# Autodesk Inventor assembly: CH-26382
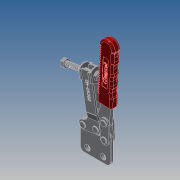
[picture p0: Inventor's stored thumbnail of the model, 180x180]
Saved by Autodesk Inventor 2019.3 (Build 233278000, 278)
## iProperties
Company: Î¢ÈíÖÐ¹ú
Created: 2012-09
Part Number: CH-26382
Material: Ogólny
Description: STEP AP203
Document SubType Name: Assembly
Designer: CADENGINEERING4
Stock Number: DOCISKI POZIOME
Sending System: SolidWorks 2010
Preprocessor: SwSTEP 2.0
Title: CH-26382.STEP
Author: Î¢ÈíÓÃ»§
Revision Number: ÈÎºÎ
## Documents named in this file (10)
- E:\STRONA\Horizontal toggle clamp\CH-26382\CH-26382_OTWARTY.iam
- E:\STRONA\Horizontal toggle clamp\CH-26382\M8.ipt
- E:\STRONA\Horizontal toggle clamp\CH-26382\01.ipt
- E:\STRONA\Horizontal toggle clamp\CH-26382\25382-04.ipt
- E:\STRONA\Horizontal toggle clamp\CH-26382\25382-05.ipt
- E:\STRONA\Horizontal toggle clamp\CH-26382\26382-02.ipt
- E:\STRONA\Horizontal toggle clamp\CH-26382\26382-01.ipt
- E:\STRONA\Horizontal toggle clamp\CH-26382\086512.ipt
- E:\STRONA\Horizontal toggle clamp\CH-26382\FW380.ipt
- E:\STRONA\Horizontal toggle clamp\CH-26382\25382-03.ipt
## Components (15 placed, 15 different names)
1. M8_1 — Równoległe:3, Zestawiające:6, Zestawiające:9
2. 01_2 — Zestawiające:1, Zestawiające:2, Zestawiające:8
3. M8_3 — Zestawiające:12, Zestawiające:13
4. 25382-04_4 — Zestawiające:15, Zestawiające:18, Zestawiające:19, Zestawiające:20, Zestawiające:21, Zestawiające:22, Zestawiające:25, Kątowe:1
5. 25382-05_5 — Zestawiające:31, Zestawiające:32
6. 25382-05_6 — Zestawiające:25, Zestawiające:33, Zestawiające:34
7. 26382-02_7 — Równoległe:1, Zestawiające:7, Zestawiające:11, Zestawiające:14, Zestawiające:26, Zestawiające:27, Zestawiające:28, Zestawiające:29, Zestawiające:30, Zestawiające:31, Zestawiające:32
8. 25382-05_8 — Zestawiające:20, Zestawiające:21
9. 26382-01_9 — Zestawiające:15, Zestawiające:16, Zestawiające:17, Zestawiające:18, Zestawiające:26, Zestawiające:27, Kątowe:1
10. 25382-04_10 — Zestawiające:16, Zestawiające:17, Zestawiające:19, Zestawiające:33
11. 086512_11 — Równoległe:3, Zestawiające:5, Zestawiające:9, Zestawiające:10, Zestawiające:12, Zestawiające:14
12. FW380_12 — Równoległe:1, Równoległe:2, Zestawiające:5, Zestawiające:6, Zestawiające:7
13. FW380_13 — Równoległe:2, Zestawiające:10, Zestawiające:11, Zestawiające:13
14. 25382-03_14 — Zestawiające:1, Zestawiające:2, Zestawiające:8, Zestawiające:22, Zestawiające:30, Zestawiające:34
15. 25382-05_15 — Zestawiające:28, Zestawiające:29
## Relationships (34: Mate 30, Flush 3, Angle 1)
- Zestawiające:1 [Mate]: 01_2 ↔ 25382-03_14
- Zestawiające:2 [Mate]: 01_2 ↔ 25382-03_14
- Równoległe:1 [Flush]: 26382-02_7 ↔ FW380_12
- Równoległe:2 [Flush]: FW380_12 ↔ FW380_13
- Równoległe:3 [Flush]: M8_1 ↔ 086512_11
- Zestawiające:5 [Mate]: 086512_11 ↔ FW380_12
- Zestawiające:6 [Mate]: M8_1 ↔ FW380_12
- Zestawiające:7 [Mate]: 26382-02_7 ↔ FW380_12
- Zestawiające:8 [Mate]: 01_2 ↔ 25382-03_14
- Zestawiające:9 [Mate]: M8_1 ↔ 086512_11
- Zestawiające:10 [Mate]: 086512_11 ↔ FW380_13
- Zestawiające:11 [Mate]: 26382-02_7 ↔ FW380_13
- Zestawiające:12 [Mate]: M8_3 ↔ 086512_11
- Zestawiające:13 [Mate]: M8_3 ↔ FW380_13
- Zestawiające:14 [Mate]: 26382-02_7 ↔ 086512_11
- Zestawiające:15 [Mate]: 25382-04_4 ↔ 26382-01_9
- Zestawiające:16 [Mate]: 26382-01_9 ↔ 25382-04_10
- Zestawiające:17 [Mate]: 26382-01_9 ↔ 25382-04_10
- Zestawiające:18 [Mate]: 25382-04_4 ↔ 26382-01_9
- Zestawiające:19 [Mate]: 25382-04_4 ↔ 25382-04_10
- Zestawiające:20 [Mate]: 25382-04_4 ↔ 25382-05_8
- Zestawiające:21 [Mate]: 25382-04_4 ↔ 25382-05_8
- Zestawiające:22 [Mate]: 25382-04_4 ↔ 25382-03_14
- Zestawiające:25 [Mate]: 25382-04_4 ↔ 25382-05_6
- Zestawiające:26 [Mate]: 26382-02_7 ↔ 26382-01_9
- Zestawiające:27 [Mate]: 26382-02_7 ↔ 26382-01_9
- Zestawiające:28 [Mate]: 26382-02_7 ↔ 25382-05_15
- Zestawiające:29 [Mate]: 26382-02_7 ↔ 25382-05_15
- Zestawiające:30 [Mate]: 26382-02_7 ↔ 25382-03_14
- Zestawiające:31 [Mate]: 25382-05_5 ↔ 26382-02_7
- Zestawiające:32 [Mate]: 25382-05_5 ↔ 26382-02_7
- Zestawiające:33 [Mate]: 25382-05_6 ↔ 25382-04_10
- Zestawiające:34 [Mate]: 25382-05_6 ↔ 25382-03_14
- Kątowe:1 [Angle]: 25382-04_4 ↔ 26382-01_9
